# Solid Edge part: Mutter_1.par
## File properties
Sűrűség: 0,000 kg/m^3
Pontosság: 0,990
Author: ahadarics
Last saved by: ahadarics
Revision: 77
Username: ahadarics
Dokumentum tartalom típus: 0
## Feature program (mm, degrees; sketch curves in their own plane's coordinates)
base feature "unnamed BaseFeature 1"
thread "unnamed Thread 1"
chamfer "Letörés_1"  SetBackValue2 = 60 deg
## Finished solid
Body 1: solid body, 23 faces, 46 edges, 24 vertices.
  Faces by surface: cone 14, plane 8, cylinder 1
  Edges by curve: spline 24, circle 16, line 6
Bounding box of the edges (mm): 6.000 x 19.630 x 17.000, from (0, -9.815, -8.5) to (6, 9.815, 8.5).
Cylindrical faces by radius (mm): R4.3235 x1
Conical faces (half-angle, radius in mm at the cone's reference point): 60 deg R4.3235 x1, 60 deg R5.0163 x1, 60 deg R9.1575 x12
Planar faces by outward normal: +x 1, +z 1, -x 1, -z 1, oblique 4
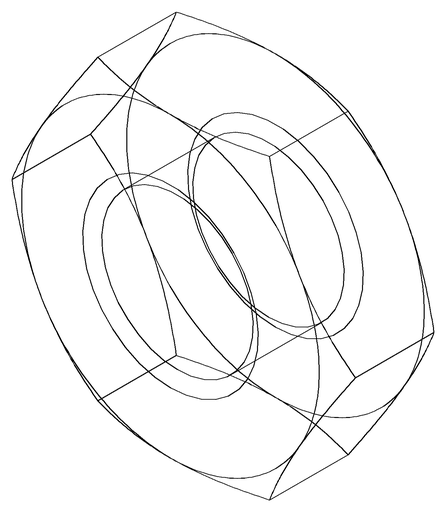
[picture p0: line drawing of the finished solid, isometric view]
